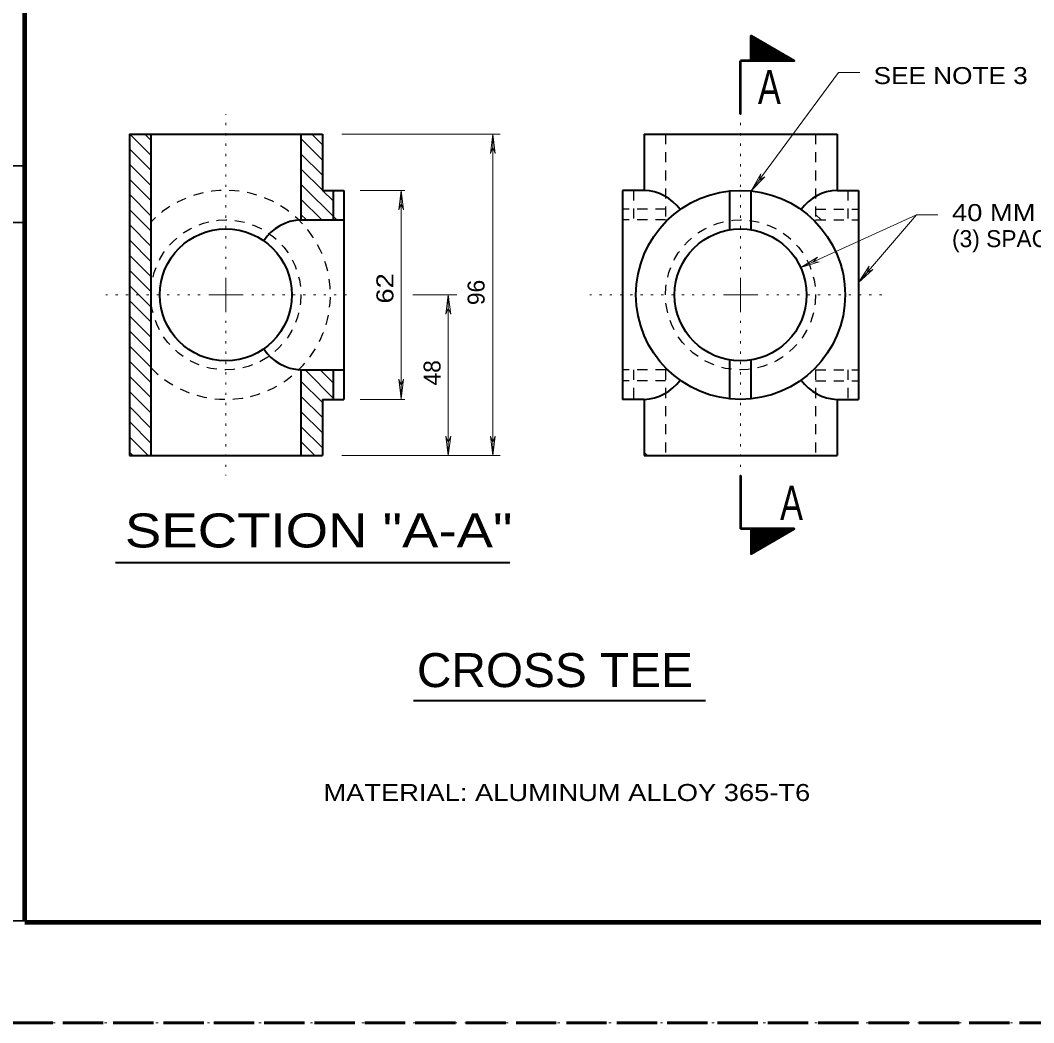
# Model space of a CAD drawing. Extents: x 312583 to 312854, y 144419 to 144597.
# Drawn here: x 312616.3 to 312661.58, y 144418.58 to 144463.41 of the extents above; entities that cross this region are included whole.
import ezdxf
from ezdxf.enums import TextEntityAlignment as Align

# ---------------------------------------------------------------- set-up
doc = ezdxf.new("R2010")
doc.units = 0
doc.header["$LTSCALE"] = 0.3
for name, pattern in [('DOTTED', [1.5, 0.3, -1.2]), ('LONG_DASHED', [7.5, 6, -1.5]), ('SHORT_DASHED', [2.7, 1.5, -1.2])]:
    doc.linetypes.add(name, pattern=pattern)
for name, color, linetype, lineweight in [('1', 7, 'Continuous', 35), ('2', 7, 'Continuous', 13), ('62', 7, 'DOTTED', 13), ('63', 7, 'LONG_DASHED', 60)]:
    doc.layers.add(name, color=color, linetype=linetype, lineweight=lineweight)

msp = doc.modelspace()

# ---------------------------------------------------------------- linework, layer by layer
at = {"layer": '1'}
for p, q in [((312648.9625, 144462.6816), (312648.9779, 144462.6969)), ((312648.9625, 144462.6356), (312649.0009, 144462.6893)), ((312648.9625, 144462.5819), (312649.0162, 144462.6739)), ((312648.9625, 144462.5359), (312649.0392, 144462.6586)), ((312648.9625, 144462.4823), (312649.0622, 144462.6509)), ((312648.9625, 144462.4439), (312649.0775, 144462.6356)), ((312648.9625, 144462.3903), (312649.1005, 144462.6279)), ((312648.9625, 144462.3443), (312649.1235, 144462.6126)), ((312648.9625, 144462.2983), (312649.1389, 144462.6049)), ((312648.9625, 144462.2523), (312649.1695, 144462.5896)), ((312648.9625, 144462.1986), (312649.1849, 144462.5819)), ((312648.9625, 144462.1526), (312649.2079, 144462.5666)), ((312648.9625, 144462.1066), (312649.2309, 144462.5589)), ((312648.9625, 144462.0529), (312649.2462, 144462.5436)), ((312648.9625, 144462.0069), (312649.2692, 144462.5359)), ((312648.9625, 144461.9609), (312649.2845, 144462.5206)), ((312648.9625, 144461.9073), (312649.3075, 144462.5053)), ((312648.9625, 144461.8613), (312649.3305, 144462.4976)), ((312648.9625, 144461.8153), (312649.3459, 144462.4823)), ((312648.9625, 144461.7693), (312649.3689, 144462.4669)), ((312648.9625, 144461.7156), (312649.3919, 144462.4593)), ((312648.9625, 144461.6773), (312649.4072, 144462.4439)), ((312648.9625, 144461.6236), (312649.4379, 144462.4363)), ((312648.9779, 144461.6006), (312649.4532, 144462.4209)), ((312649.0085, 144461.6006), (312649.4762, 144462.4133)), ((312649.0392, 144461.6006), (312649.4992, 144462.3979)), ((312649.0622, 144461.6006), (312649.5145, 144462.3903)), ((312649.0929, 144461.6006), (312649.5375, 144462.3749)), ((312649.1159, 144461.6083), (312649.5605, 144462.3673)), ((312649.1465, 144461.6083), (312649.5759, 144462.3519)), ((312649.1695, 144461.6006), (312649.5989, 144462.3443)), ((312649.2002, 144461.6006), (312649.6219, 144462.3289)), ((312649.2309, 144461.6006), (312649.6372, 144462.3136)), ((312649.2539, 144461.6006), (312649.6602, 144462.3059)), ((312649.2845, 144461.6006), (312649.6832, 144462.2906)), ((312649.3152, 144461.6006), (312649.7062, 144462.2753)), ((312649.3382, 144461.6006), (312649.7215, 144462.2676)), ((312649.3689, 144461.6083), (312649.7445, 144462.2523)), ((312649.3995, 144461.6006), (312649.7675, 144462.2446)), ((312649.4225, 144461.6006), (312649.7829, 144462.2293)), ((312649.4455, 144461.6006), (312649.8059, 144462.2216)), ((312649.4762, 144461.6006), (312649.8289, 144462.2063)), ((312649.5069, 144461.6006), (312649.8442, 144462.1986)), ((312649.5375, 144461.6006), (312649.8672, 144462.1833)), ((312649.5605, 144461.6006), (312649.8902, 144462.1756)), ((312649.5912, 144461.6006), (312649.9055, 144462.1603)), ((312649.6142, 144461.6083), (312649.9362, 144462.1526)), ((312649.6449, 144461.6006), (312649.9515, 144462.1373)), ((312649.6679, 144461.6006), (312649.9745, 144462.1219)), ((312649.6985, 144461.6006), (312649.9975, 144462.1143)), ((312649.7292, 144461.6006), (312650.0129, 144462.0989)), ((312649.7522, 144461.6006), (312650.0359, 144462.0913)), ((312649.7829, 144461.6006), (312650.0589, 144462.0759)), ((312649.8135, 144461.6006), (312650.0742, 144462.0683)), ((312649.8365, 144461.6006), (312650.0972, 144462.0529)), ((312649.8672, 144461.6006), (312650.1202, 144462.0453)), ((312649.8979, 144461.6006), (312650.1355, 144462.0299)), ((312649.9209, 144461.6006), (312650.1585, 144462.0223)), ((312649.9439, 144461.6006), (312650.1815, 144462.0069)), ((312649.9745, 144461.6006), (312650.2045, 144461.9993)), ((312650.0052, 144461.6006), (312650.2199, 144461.9839)), ((312650.0359, 144461.6006), (312650.2429, 144461.9686)), ((312650.0589, 144461.6006), (312650.2659, 144461.9609)), ((312650.0895, 144461.6006), (312650.2812, 144461.9456)), ((312650.1125, 144461.6006), (312650.3042, 144461.9303)), ((312650.1432, 144461.6006), (312650.3272, 144461.9226)), ((312650.1662, 144461.6006), (312650.3425, 144461.9073)), ((312650.1969, 144461.6006), (312650.3655, 144461.8996)), ((312650.2275, 144461.6006), (312650.3885, 144461.8843)), ((312650.2505, 144461.6006), (312650.4039, 144461.8766)), ((312650.2812, 144461.6006), (312650.4345, 144461.8613)), ((312650.3042, 144461.6006), (312650.4499, 144461.8536)), ((312650.3349, 144461.6006), (312650.4729, 144461.8383)), ((312650.3655, 144461.6006), (312650.4959, 144461.8306)), ((312650.3885, 144461.6006), (312650.5112, 144461.8153)), ((312650.4192, 144461.6006), (312650.5342, 144461.8076)), ((312650.4422, 144461.6006), (312650.5572, 144461.7923)), ((312650.4729, 144461.6006), (312650.5725, 144461.7769)), ((312650.5035, 144461.6006), (312650.5955, 144461.7693)), ((312650.5342, 144461.6006), (312650.6185, 144461.7539)), ((312650.5572, 144461.6006), (312650.6339, 144461.7386)), ((312650.5879, 144461.6006), (312650.6569, 144461.7309)), ((312650.6109, 144461.6006), (312650.6799, 144461.7156)), ((312650.6339, 144461.6006), (312650.7029, 144461.7079)), ((312650.6645, 144461.6006), (312650.7182, 144461.6926)), ((312650.6952, 144461.6006), (312650.7412, 144461.6849)), ((312650.7259, 144461.6006), (312650.7642, 144461.6696)), ((312650.7489, 144461.6006), (312650.7795, 144461.6619)), ((312650.7795, 144461.6006), (312650.8025, 144461.6466)), ((312650.8025, 144461.6006), (312650.8255, 144461.6389)), ((312650.8332, 144461.6006), (312650.8409, 144461.6236)), ((312650.8639, 144461.6006), (312650.8639, 144461.6159)), ((312648.9625, 144440.6399), (312649.4379, 144439.8273)), ((312648.9625, 144440.5863), (312649.4072, 144439.8196)), ((312648.9625, 144440.5479), (312649.3919, 144439.8043)), ((312648.9625, 144440.4943), (312649.3689, 144439.7966)), ((312648.9625, 144440.4483), (312649.3459, 144439.7813)), ((312648.9625, 144440.4023), (312649.3305, 144439.7659)), ((312648.9625, 144440.3563), (312649.3075, 144439.7583)), ((312648.9625, 144440.3026), (312649.2845, 144439.7429)), ((312648.9779, 144440.6629), (312649.4532, 144439.8426)), ((312649.0085, 144440.6629), (312649.4762, 144439.8503)), ((312649.0392, 144440.6629), (312649.4992, 144439.8656)), ((312649.0622, 144440.6629), (312649.5145, 144439.8733)), ((312649.0929, 144440.6629), (312649.5375, 144439.8886)), ((312649.1159, 144440.6553), (312649.5605, 144439.8963)), ((312649.1465, 144440.6553), (312649.5759, 144439.9116)), ((312649.1695, 144440.6629), (312649.5989, 144439.9193)), ((312649.2002, 144440.6629), (312649.6219, 144439.9346)), ((312649.2309, 144440.6629), (312649.6372, 144439.9499)), ((312649.2539, 144440.6629), (312649.6602, 144439.9576)), ((312649.2845, 144440.6629), (312649.6832, 144439.9729)), ((312649.3152, 144440.6629), (312649.7062, 144439.9883)), ((312649.3382, 144440.6629), (312649.7215, 144439.9959)), ((312649.3689, 144440.6553), (312649.7445, 144440.0113)), ((312649.3995, 144440.6629), (312649.7675, 144440.0189)), ((312649.4225, 144440.6629), (312649.7829, 144440.0343)), ((312649.4455, 144440.6629), (312649.8059, 144440.0419)), ((312649.4762, 144440.6629), (312649.8289, 144440.0573)), ((312649.5069, 144440.6629), (312649.8442, 144440.0649)), ((312649.5375, 144440.6629), (312649.8672, 144440.0803)), ((312649.5605, 144440.6629), (312649.8902, 144440.0879)), ((312649.5912, 144440.6629), (312649.9055, 144440.1033)), ((312649.6142, 144440.6553), (312649.9362, 144440.1109)), ((312649.6449, 144440.6629), (312649.9515, 144440.1263)), ((312649.6679, 144440.6629), (312649.9745, 144440.1416)), ((312649.6985, 144440.6629), (312649.9975, 144440.1493)), ((312649.7292, 144440.6629), (312650.0129, 144440.1646)), ((312649.7522, 144440.6629), (312650.0359, 144440.1723)), ((312649.7829, 144440.6629), (312650.0589, 144440.1876)), ((312649.8135, 144440.6629), (312650.0742, 144440.1953)), ((312649.8365, 144440.6629), (312650.0972, 144440.2106)), ((312649.8672, 144440.6629), (312650.1202, 144440.2183)), ((312649.8979, 144440.6629), (312650.1355, 144440.2336)), ((312649.9209, 144440.6629), (312650.1585, 144440.2413)), ((312649.9439, 144440.6629), (312650.1815, 144440.2566)), ((312649.9745, 144440.6629), (312650.2045, 144440.2643)), ((312650.0052, 144440.6629), (312650.2199, 144440.2796)), ((312650.0359, 144440.6629), (312650.2429, 144440.2949)), ((312650.0589, 144440.6629), (312650.2659, 144440.3026)), ((312650.0895, 144440.6629), (312650.2812, 144440.3179)), ((312650.1125, 144440.6629), (312650.3042, 144440.3333)), ((312650.1432, 144440.6629), (312650.3272, 144440.3409)), ((312650.1662, 144440.6629), (312650.3425, 144440.3563)), ((312650.1969, 144440.6629), (312650.3655, 144440.3639)), ((312650.2275, 144440.6629), (312650.3885, 144440.3793)), ((312650.2505, 144440.6629), (312650.4039, 144440.3869)), ((312650.2812, 144440.6629), (312650.4345, 144440.4023)), ((312650.3042, 144440.6629), (312650.4499, 144440.4099)), ((312650.3349, 144440.6629), (312650.4729, 144440.4253)), ((312650.3655, 144440.6629), (312650.4959, 144440.4329)), ((312650.3885, 144440.6629), (312650.5112, 144440.4483)), ((312650.4192, 144440.6629), (312650.5342, 144440.4559)), ((312650.4422, 144440.6629), (312650.5572, 144440.4713)), ((312650.4729, 144440.6629), (312650.5725, 144440.4866)), ((312650.5035, 144440.6629), (312650.5955, 144440.4943)), ((312650.5342, 144440.6629), (312650.6185, 144440.5096)), ((312650.5572, 144440.6629), (312650.6339, 144440.5249)), ((312650.5879, 144440.6629), (312650.6569, 144440.5326)), ((312650.6109, 144440.6629), (312650.6799, 144440.5479)), ((312650.6339, 144440.6629), (312650.7029, 144440.5556)), ((312650.6645, 144440.6629), (312650.7182, 144440.5709)), ((312650.6952, 144440.6629), (312650.7412, 144440.5786)), ((312650.7259, 144440.6629), (312650.7642, 144440.5939)), ((312650.7489, 144440.6629), (312650.7795, 144440.6016)), ((312650.7795, 144440.6629), (312650.8025, 144440.6169)), ((312650.8025, 144440.6629), (312650.8255, 144440.6246)), ((312650.8332, 144440.6629), (312650.8409, 144440.6399)), ((312650.8639, 144440.6629), (312650.8639, 144440.6476)), ((312648.9625, 144440.2566), (312649.2692, 144439.7276)), ((312648.9625, 144440.2106), (312649.2462, 144439.7199)), ((312648.9625, 144440.1569), (312649.2309, 144439.7046)), ((312648.9625, 144440.1109), (312649.2079, 144439.6969)), ((312648.9625, 144440.0649), (312649.1849, 144439.6816)), ((312648.9625, 144440.0113), (312649.1695, 144439.6739)), ((312648.9625, 144439.9653), (312649.1389, 144439.6586)), ((312648.9625, 144439.9193), (312649.1235, 144439.6509)), ((312648.9625, 144439.8733), (312649.1005, 144439.6356)), ((312648.9625, 144439.8196), (312649.0775, 144439.6279)), ((312648.9625, 144439.7813), (312649.0622, 144439.6126)), ((312648.9625, 144439.7276), (312649.0392, 144439.6049)), ((312648.9625, 144439.6816), (312649.0162, 144439.5896)), ((312648.9625, 144439.6279), (312649.0009, 144439.5743)), ((312648.9625, 144439.5819), (312648.9779, 144439.5666))]:
    msp.add_line(p, q, dxfattribs=at)
at = {"layer": '1', "lineweight": 53}
for p, q in [((312648.4872, 144459.2086), (312648.4872, 144461.6006)), ((312648.9625, 144461.6006), (312648.4872, 144461.6006)), ((312648.4872, 144443.0549), (312648.4872, 144440.6629)), ((312648.9625, 144440.6629), (312648.4872, 144440.6629))]:
    msp.add_line(p, q, dxfattribs=at)
at = {"layer": '1', "lineweight": 40}
for p, q in [((312621.1709, 144458.3193), (312629.7959, 144458.3193)), ((312621.1709, 144458.3193), (312621.1709, 144443.9443)), ((312622.1292, 144458.3193), (312622.1292, 144443.9443)), ((312628.8375, 144458.3193), (312628.8375, 144454.4859)), ((312629.7959, 144458.3193), (312629.7959, 144455.8046)), ((312644.1709, 144458.3193), (312652.7959, 144458.3193)), ((312644.1709, 144458.3193), (312644.1709, 144455.8046)), ((312652.7959, 144458.3193), (312652.7959, 144455.8046)), ((312629.7959, 144455.8046), (312630.7542, 144455.8046)), ((312630.2789, 144455.8046), (312630.2789, 144454.4859)), ((312630.7542, 144455.8046), (312630.7542, 144446.4589)), ((312643.2125, 144455.8046), (312643.2125, 144446.4589)), ((312644.1709, 144455.8046), (312643.2125, 144455.8046)), ((312648.0042, 144454.0413), (312648.0042, 144455.7816)), ((312648.9625, 144454.0413), (312648.9625, 144455.7816)), ((312652.7959, 144455.8046), (312653.7542, 144455.8046)), ((312653.7542, 144455.8046), (312653.7542, 144446.4589)), ((312628.8375, 144454.4859), (312630.7542, 144454.4859)), ((312648.0042, 144446.4819), (312648.0042, 144448.2146)), ((312648.9625, 144446.4819), (312648.9625, 144448.2146)), ((312628.8375, 144447.7776), (312630.7542, 144447.7776)), ((312628.8375, 144447.7776), (312628.8375, 144443.9443)), ((312630.2789, 144447.7776), (312630.2789, 144446.4589)), ((312629.7959, 144446.4589), (312630.7542, 144446.4589)), ((312629.7959, 144446.4589), (312629.7959, 144443.9443)), ((312644.1709, 144446.4589), (312643.2125, 144446.4589)), ((312644.1709, 144446.4589), (312644.1709, 144443.9443)), ((312652.7959, 144446.4589), (312653.7542, 144446.4589)), ((312652.7959, 144446.4589), (312652.7959, 144443.9443)), ((312621.1709, 144443.9443), (312629.7959, 144443.9443)), ((312644.1709, 144443.9443), (312652.7959, 144443.9443))]:
    msp.add_line(p, q, dxfattribs=at)
at = {"layer": '1', "linetype": 'SHORT_DASHED', "lineweight": 25}
for p, q in [((312645.1292, 144458.3193), (312645.1292, 144454.4859)), ((312651.8375, 144458.3193), (312651.8375, 144454.4859)), ((312643.6955, 144455.8046), (312643.6955, 144454.4859)), ((312653.2789, 144455.8046), (312653.2789, 144454.4859)), ((312645.1292, 144454.9613), (312643.2125, 144454.9613)), ((312651.8375, 144454.9613), (312653.7542, 144454.9613)), ((312645.1292, 144454.4859), (312643.2125, 144454.4859)), ((312651.8375, 144454.4859), (312653.7542, 144454.4859)), ((312645.1292, 144447.7776), (312643.2125, 144447.7776)), ((312643.6955, 144447.7776), (312643.6955, 144446.4589)), ((312645.1292, 144447.7776), (312645.1292, 144443.9443)), ((312651.8375, 144447.7776), (312653.7542, 144447.7776)), ((312651.8375, 144447.7776), (312651.8375, 144443.9443)), ((312653.2789, 144447.7776), (312653.2789, 144446.4589)), ((312645.1292, 144447.2946), (312643.2125, 144447.2946)), ((312651.8375, 144447.2946), (312653.7542, 144447.2946))]:
    msp.add_line(p, q, dxfattribs=at)
at = {"layer": '1', "lineweight": 158}
msp.add_line((312616.5, 144423.0846), (312849, 144423.0846), dxfattribs=at)
msp.add_lwpolyline([(312616.5, 144423.1446), (312616.5, 144585.0846), (312849, 144585.0846)], dxfattribs=at)
at = {"layer": '1'}
for points in [[(312616.5, 144456.901), (312608.8858, 144456.901), (312608.8858, 144488.1192), (312616.5, 144488.1192)], [(312616.5, 144423.1446), (312608.8858, 144423.1446), (312608.8858, 144454.3629), (312616.5, 144454.3629)]]:
    msp.add_lwpolyline(points, dxfattribs=at)
at = {"layer": '1', "lineweight": 53}
for points in [[(312648.9625, 144461.6006), (312648.9625, 144462.7123), (312650.8792, 144461.6006)], [(312648.9625, 144440.6629), (312648.9625, 144439.5513), (312650.8792, 144440.6629)]]:
    msp.add_lwpolyline(points, close=True, dxfattribs=at)
at = {"layer": '1', "lineweight": 40}
for centre, radius in [((312648.4834, 144451.1318), 4.6728), ((312625.4834, 144451.1318), 2.9517), ((312648.4834, 144451.1318), 2.9517)]:
    msp.add_circle(centre, radius, dxfattribs=at)
at = {"layer": '1', "linetype": 'SHORT_DASHED', "lineweight": 25}
for centre in [(312625.4834, 144451.1318), (312648.4834, 144451.1318)]:
    msp.add_circle(centre, 3.3542, dxfattribs=at)
msp.add_arc((312625.4834, 144451.1318), 4.6728, 224.12674, 135.86402, dxfattribs=at)
at = {"layer": '1', "lineweight": 40}
for centre, start, end in [((312644.0885, 144453.7173), 35.93098, 87.73881), ((312652.8783, 144453.7173), 92.26119, 144.06902), ((312628.92, 144452.3987), 92.26119, 146.57116), ((312628.92, 144449.8649), 213.42884, 267.73881), ((312644.0885, 144448.5462), 272.26119, 324.06902), ((312652.8783, 144448.5462), 215.93098, 267.73881)]:
    msp.add_arc(centre, 2.0889, start, end, dxfattribs=at)
at = {"layer": '2'}
for p, q in [((312648.9625, 144455.7816), (312652.8572, 144461.0716)), ((312652.8572, 144461.0716), (312653.8079, 144461.0716)), ((312621.1862, 144458.3193), (312622.1292, 144457.3763)), ((312621.8609, 144458.3193), (312622.1292, 144458.0509)), ((312628.8375, 144458.1199), (312629.7959, 144457.1616)), ((312629.3205, 144458.3193), (312629.7959, 144457.8439)), ((312630.6699, 144458.3193), (312637.7385, 144458.3193)), ((312637.4165, 144458.3193), (312637.3092, 144457.4529)), ((312637.4165, 144443.9443), (312637.4165, 144458.3193)), ((312637.4165, 144458.3193), (312637.5239, 144457.4529)), ((312621.1709, 144457.6599), (312622.1292, 144456.7016)), ((312637.3092, 144457.4529), (312637.4165, 144457.7289)), ((312637.5239, 144457.4529), (312637.4165, 144457.7289)), ((312628.8375, 144457.4453), (312629.7959, 144456.4869)), ((312621.1709, 144456.9776), (312622.1292, 144456.0193)), ((312628.8375, 144456.7706), (312629.7959, 144455.8123)), ((312621.1709, 144456.3029), (312622.1292, 144455.3446)), ((312648.9625, 144455.7816), (312649.3919, 144456.5406)), ((312648.9625, 144455.7816), (312649.5682, 144456.4103)), ((312649.3919, 144456.5406), (312649.3152, 144456.2569)), ((312649.5682, 144456.4103), (312649.3152, 144456.2569)), ((312628.8375, 144456.0883), (312630.4399, 144454.4859)), ((312629.8035, 144455.8046), (312630.2789, 144455.3293)), ((312631.4902, 144455.8046), (312633.4759, 144455.8046)), ((312633.3149, 144455.8046), (312633.2075, 144454.9383)), ((312633.3149, 144446.4896), (312633.3149, 144455.8046)), ((312633.3149, 144455.8046), (312633.4222, 144454.9383)), ((312621.1709, 144455.6283), (312622.1292, 144454.6699)), ((312628.8375, 144455.4136), (312629.7652, 144454.4859)), ((312621.1709, 144454.9459), (312622.1292, 144453.9876)), ((312633.2075, 144454.9383), (312633.3149, 144455.2143)), ((312633.4222, 144454.9383), (312633.3149, 144455.2143)), ((312628.8375, 144454.7313), (312629.0829, 144454.4859)), ((312651.8375, 144454.7313), (312652.0829, 144454.4859)), ((312656.3455, 144454.7159), (312657.2962, 144454.7159)), ((312621.1709, 144454.2713), (312622.1292, 144453.3129)), ((312621.1709, 144453.5889), (312622.1292, 144452.6306)), ((312621.1709, 144452.9143), (312622.1292, 144451.9559)), ((312651.1705, 144452.3546), (312651.9142, 144452.8146)), ((312651.1705, 144452.3546), (312651.9985, 144452.6153)), ((312651.9142, 144452.8146), (312651.7072, 144452.5999)), ((312651.9985, 144452.6153), (312651.7072, 144452.5999)), ((312621.1709, 144452.2396), (312622.1292, 144451.2813)), ((312653.7542, 144451.6799), (312654.2372, 144452.4083)), ((312653.7542, 144451.6799), (312654.3982, 144452.2703)), ((312654.2372, 144452.4083), (312654.1375, 144452.1323)), ((312654.3982, 144452.2703), (312654.1375, 144452.1323)), ((312625.4872, 144451.1279), (312625.4872, 144451.8946)), ((312648.4872, 144451.1279), (312648.4872, 144451.8946)), ((312621.1709, 144451.5573), (312622.1292, 144450.5989)), ((312621.1709, 144450.8826), (312622.1292, 144449.9243)), ((312625.4872, 144451.1279), (312624.7205, 144451.1279)), ((312625.4872, 144451.1279), (312625.4872, 144450.3613)), ((312625.4872, 144451.1279), (312626.2539, 144451.1279)), ((312633.8439, 144451.1279), (312635.8065, 144451.1279)), ((312635.4232, 144451.1279), (312635.3159, 144450.2616)), ((312635.4232, 144443.9443), (312635.4232, 144451.1279)), ((312635.4232, 144451.1279), (312635.5305, 144450.2616)), ((312648.4872, 144451.1279), (312647.7205, 144451.1279)), ((312648.4872, 144451.1279), (312649.2539, 144451.1279)), ((312648.4872, 144451.1279), (312648.4872, 144450.3613)), ((312635.3159, 144450.2616), (312635.4232, 144450.5376)), ((312635.5305, 144450.2616), (312635.4232, 144450.5376)), ((312621.1709, 144450.2003), (312622.1292, 144449.2419)), ((312621.1709, 144449.5256), (312622.1292, 144448.5673)), ((312621.1709, 144448.8509), (312622.1292, 144447.8926)), ((312621.1709, 144448.1686), (312622.1292, 144447.2103)), ((312629.0215, 144447.7776), (312630.3402, 144446.4589)), ((312629.6962, 144447.7776), (312630.2789, 144447.1949)), ((312621.1709, 144447.4939), (312622.1292, 144446.5356)), ((312628.8375, 144447.2793), (312629.7959, 144446.3209)), ((312633.2075, 144447.3559), (312633.3149, 144447.0799)), ((312633.3149, 144446.4896), (312633.2075, 144447.3559)), ((312633.4222, 144447.3559), (312633.3149, 144447.0799)), ((312633.3149, 144446.4896), (312633.4222, 144447.3559)), ((312621.1709, 144446.8116), (312622.1292, 144445.8533)), ((312628.8375, 144446.6046), (312629.7959, 144445.6463)), ((312631.4902, 144446.4589), (312633.4759, 144446.4589)), ((312621.1709, 144446.1369), (312622.1292, 144445.1786)), ((312628.8375, 144445.9223), (312629.7959, 144444.9639)), ((312621.1709, 144445.4623), (312622.1292, 144444.5039)), ((312628.8375, 144445.2476), (312629.7959, 144444.2893)), ((312621.1709, 144444.7799), (312622.0065, 144443.9443)), ((312628.8375, 144444.5729), (312629.4662, 144443.9443)), ((312635.3159, 144444.8106), (312635.4232, 144444.5346)), ((312635.4232, 144443.9443), (312635.3159, 144444.8106)), ((312635.5305, 144444.8106), (312635.4232, 144444.5346)), ((312635.4232, 144443.9443), (312635.5305, 144444.8106)), ((312637.3092, 144444.8106), (312637.4165, 144444.5346)), ((312637.4165, 144443.9443), (312637.3092, 144444.8106)), ((312637.5239, 144444.8106), (312637.4165, 144444.5346)), ((312637.4165, 144443.9443), (312637.5239, 144444.8106)), ((312621.1709, 144444.1053), (312621.3319, 144443.9443)), ((312630.6699, 144443.9443), (312637.7385, 144443.9443)), ((312644.1709, 144444.1053), (312644.3319, 144443.9443))]:
    msp.add_line(p, q, dxfattribs=at)
at = {"layer": '2', "linetype": 'DOTTED'}
for p, q in [((312648.4872, 144452.2779), (312648.4872, 144459.9446)), ((312625.4872, 144452.2779), (312625.4872, 144459.2163)), ((312624.3372, 144451.1279), (312620.1205, 144451.1279)), ((312626.6372, 144451.1279), (312631.1069, 144451.1279)), ((312647.3372, 144451.1279), (312641.7482, 144451.1279)), ((312649.6372, 144451.1279), (312655.1265, 144451.1279)), ((312625.4872, 144449.9779), (312625.4872, 144443.0549)), ((312648.4872, 144449.9779), (312648.4872, 144442.3113))]:
    msp.add_line(p, q, dxfattribs=at)
at = {"layer": '2', "lineweight": 40}
for p, q in [((312620.5471, 144439.1603), (312638.1731, 144439.1603)), ((312633.8741, 144432.9886), (312646.9144, 144432.9886))]:
    msp.add_line(p, q, dxfattribs=at)
at = {"layer": '2'}
msp.add_lwpolyline([(312651.1705, 144452.3546), (312656.3455, 144454.7159), (312653.7542, 144451.6799)], dxfattribs=at)
at = {"layer": '62'}
msp.add_lwpolyline([(312601.2, 144418.5846), (312853.5, 144418.5846), (312853.5, 144596.7846)], dxfattribs=at)
at = {"layer": '63'}
msp.add_line((312851.75, 144418.5846), (312583.526, 144418.5846), dxfattribs=at)

# ---------------------------------------------------------------- texts
at = {"layer": '1', "width": 0.75}
for p in [(312649.7714, 144459.6609), (312650.7604, 144441.0616)]:
    msp.add_text('A', height=1.533, dxfattribs=at).set_placement(p, align=Align.CENTER)
at = {"layer": '2'}
for s, height, width, p in [('SEE NOTE 3', 0.76, 1.15, (312654.4292, 144460.5574)), ('40 MM NPT', 0.76, 1.2, (312657.9325, 144454.4312)), ('SECTION "A-A"', 1.52, 1.2, (312620.9712, 144439.8363)), ('CROSS TEE', 1.52, 1.05, (312634.023, 144433.5928)), ('MATERIAL: ALUMINUM ALLOY 365-T6', 0.76, 1.2, (312629.8415, 144428.5003))]:
    msp.add_text(s, height=height, dxfattribs=dict(at, width=width)).set_placement(p)
msp.add_text('(3) SPACES', height=0.76, dxfattribs=at).set_placement((312657.9325, 144453.2649))
at = {"layer": '2', "width": 1.2}
msp.add_text('62 ', height=0.76, rotation=90, dxfattribs=at).set_placement((312632.9701, 144450.7432))
at = {"layer": '2'}
for s, p in [('96', (312637.0464, 144450.6749)), ('48', (312635.0784, 144447.0805))]:
    msp.add_text(s, height=0.76, rotation=90, dxfattribs=at).set_placement(p)

doc.saveas('drawing.dxf')
